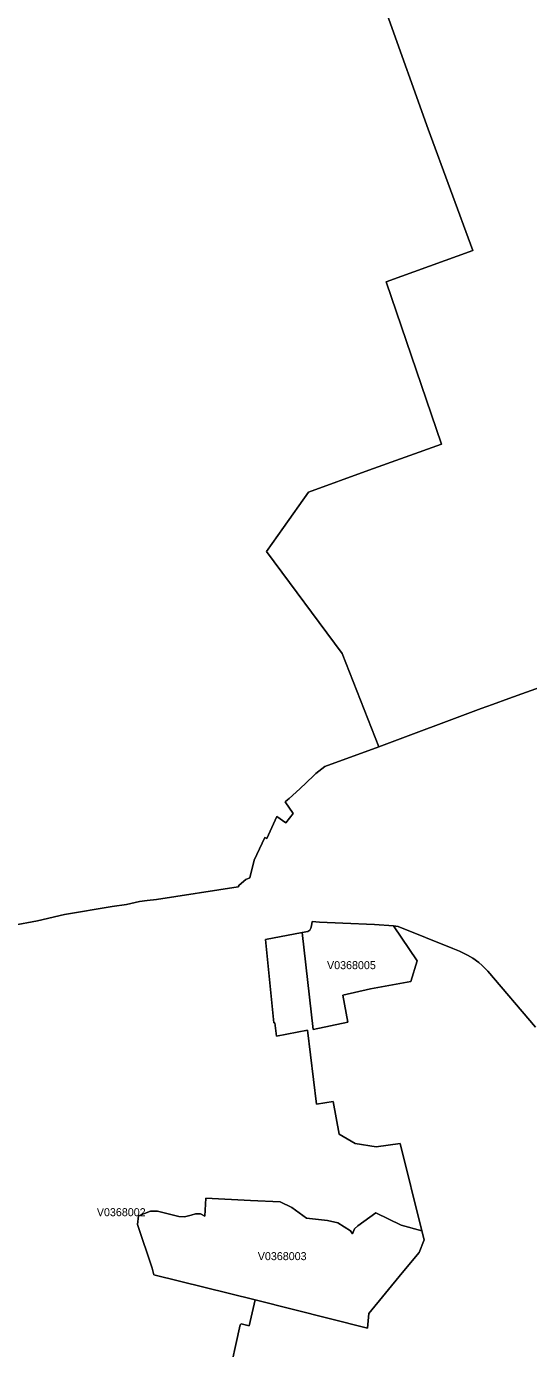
# Model space of a CAD drawing. Extents: x 369010 to 735936, y 6377141 to 6616555.
# Drawn here: x 420580 to 426855, y 6521309 to 6537827 of the extents above; entities that cross this region are included whole.
import ezdxf
from ezdxf.enums import TextEntityAlignment as Align

# ---------------------------------------------------------------- set-up
doc = ezdxf.new("R2010")
doc.units = 0
doc.header["$LTSCALE"] = 40
doc.layers.add('3', color=7, linetype='Continuous', lineweight=13)
doc.layers.add('4', color=7, linetype='Continuous')

msp = doc.modelspace()

# ---------------------------------------------------------------- linework, layer by layer
at = {"layer": '3'}
for points in [[(424415.81, 6546307.59), (424374.6, 6546292.36), (424272.82, 6546261.91), (423933.2, 6546139.93), (422029.25, 6545457.73), (423467.15, 6541434.49), (423806.93, 6541545.87), (424061.64, 6540845.46), (425600.49, 6536542.36), (426160.06, 6535027.83), (425074.19, 6534636.25), (425765.33, 6532609.98), (424859.86, 6532281.79), (424104.67, 6532007.05), (423793.52, 6531567.14), (423578.53, 6531267.41), (424524.72, 6529994.03), (424983.49, 6528828.21), (426261.85, 6529304.37), (426404.84, 6529356.34), (426607.91, 6529430.15), (427110.22, 6529610.72)], [(423226.67, 6527076.19), (423237.92, 6527099.36), (423323.16, 6527167.55), (423370.99, 6527189.39), (423426.43, 6527412.82), (423492.3, 6527553.83), (423558.34, 6527694.84), (423582.83, 6527682.76), (423711.43, 6527957.5), (423821.49, 6527876.07), (423915.33, 6527993.08), (423815.03, 6528138.56), (423843.34, 6528163.39), (423863.69, 6528180.43), (423998.58, 6528303.9), (424168.88, 6528465.1), (424195.69, 6528491.91), (424307.91, 6528582.61), (424983.49, 6528828.21), (424524.72, 6529994.03), (423578.53, 6531267.41), (423793.52, 6531567.14), (424104.67, 6532007.05), (424859.86, 6532281.79), (425765.33, 6532609.98), (425074.19, 6534636.25), (426160.06, 6535027.83), (425600.49, 6536542.36), (424061.64, 6540845.46)], [(427110.22, 6529610.72), (426607.91, 6529430.15), (426404.84, 6529356.34), (426261.85, 6529304.37), (424983.49, 6528828.21)], [(424983.49, 6528828.21), (424307.91, 6528582.61), (424195.69, 6528491.91), (424168.88, 6528465.1), (423998.58, 6528303.9), (423863.69, 6528180.43), (423843.34, 6528163.39), (423815.03, 6528138.56), (423915.33, 6527993.08), (423821.49, 6527876.07), (423711.43, 6527957.5), (423582.83, 6527682.76), (423558.34, 6527694.84), (423492.3, 6527553.83), (423426.43, 6527412.82), (423370.99, 6527189.39), (423323.16, 6527167.55), (423237.92, 6527099.36), (423226.67, 6527076.19), (422206, 6526921.61), (422089.66, 6526908.53), (421991.02, 6526894.3), (421830.81, 6526856.9), (421650.57, 6526833.23), (421056.08, 6526732.27), (420717.3, 6526654.49), (420407.64, 6526594.74)], [(420407.64, 6526594.74), (420717.3, 6526654.49), (421056.08, 6526732.27), (421650.57, 6526833.23), (421830.81, 6526856.9), (421991.02, 6526894.3), (422089.66, 6526908.53), (422206, 6526921.61), (423226.67, 6527076.19)], [(426940.08, 6525323.67), (426344.76, 6526022.43), (426276.91, 6526095.74), (426234.87, 6526134.31), (426157.74, 6526186.94), (426093.03, 6526223.68), (425991.41, 6526272.67), (425909.16, 6526309.41), (425226.78, 6526580.84), (425169.35, 6526590.1), (425461.3, 6526153.5), (425386, 6525894.33), (424878.89, 6525805.28), (424535.64, 6525724.68), (424598.7, 6525388.55), (424161.77, 6525297.52), (424026.88, 6526505.7), (423567.77, 6526421.12), (423672.7, 6525377.29), (423683.29, 6525378.28), (423704.31, 6525211.79), (424091.26, 6525288.91), (424203.14, 6524361.59), (424413.33, 6524394.86), (424488.64, 6523986.89), (424690.05, 6523871.2), (424949.23, 6523830.99), (425250.29, 6523871.2), (425522.21, 6522781.86), (425550.84, 6522667.33), (425486.13, 6522509.77), (425275.94, 6522255.89), (424861.19, 6521747.95), (424843.97, 6521564.58), (423440.5, 6521918.42), (423363.71, 6521593.54), (423265.56, 6521616.87), (423249.51, 6521604.3), (423095.92, 6520904.55)], [(424690.05, 6523871.2), (424488.64, 6523986.89), (424413.33, 6524394.86), (424203.14, 6524361.59), (424091.26, 6525288.91), (423704.31, 6525211.79), (423683.29, 6525378.28), (423672.7, 6525377.29), (423567.77, 6526421.12), (424026.88, 6526505.7), (424096.89, 6526520.59), (424121.38, 6526534.66), (424135.45, 6526559.98), (424143.39, 6526592.42), (424151.17, 6526645.05), (424241.37, 6526637.94), (424534.65, 6526623.04), (424928.88, 6526608.31), (425169.35, 6526590.1), (425226.78, 6526580.84), (425909.16, 6526309.41), (425991.41, 6526272.67), (426093.03, 6526223.68), (426157.74, 6526186.94), (426234.87, 6526134.31), (426276.91, 6526095.74), (426344.76, 6526022.43), (426940.08, 6525323.67)], [(423095.92, 6520904.55), (423249.51, 6521604.3), (423265.56, 6521616.87), (423363.71, 6521593.54), (423440.5, 6521918.42), (422173.4, 6522232.22), (422152.22, 6522312.65), (421968.34, 6522859.15), (421982.24, 6522966.06), (422129.38, 6523023.82), (422216.93, 6523025.48), (422285.28, 6523009.76), (422483.06, 6522957.29), (422556.71, 6522955.47), (422640.62, 6522976.49), (422693.25, 6522994.03), (422754.49, 6522990.56), (422808.77, 6522964.24), (422821.02, 6523188.34), (423379.59, 6523160.37), (423749.99, 6523144.48), (423895.3, 6523072.65), (424079.18, 6522939.58), (424343.49, 6522908.14), (424470.43, 6522880.33), (424629.81, 6522778.71), (424654.31, 6522741.97), (424678.8, 6522803.21), (424720.84, 6522841.77), (424946.75, 6523004.63), (425263.03, 6522850.21), (425522.21, 6522781.86), (425250.29, 6523871.2), (424949.23, 6523830.99), (424690.05, 6523871.2)]]:
    msp.add_lwpolyline(points, dxfattribs=at)
for points in [[(424026.88, 6526505.7), (424161.77, 6525297.52), (424598.7, 6525388.55), (424535.64, 6525724.68), (424878.89, 6525805.28), (425386, 6525894.33), (425461.3, 6526153.5), (425169.35, 6526590.1), (424928.88, 6526608.31), (424534.65, 6526623.04), (424241.37, 6526637.94), (424151.17, 6526645.05), (424143.39, 6526592.42), (424135.45, 6526559.98), (424121.38, 6526534.66), (424096.89, 6526520.59)], [(423440.5, 6521918.42), (424843.97, 6521564.58), (424861.19, 6521747.95), (425275.94, 6522255.89), (425486.13, 6522509.77), (425550.84, 6522667.33), (425522.21, 6522781.86), (425263.03, 6522850.21), (424946.75, 6523004.63), (424720.84, 6522841.77), (424678.8, 6522803.21), (424654.31, 6522741.97), (424629.81, 6522778.71), (424470.43, 6522880.33), (424343.49, 6522908.14), (424079.18, 6522939.58), (423895.3, 6523072.65), (423749.99, 6523144.48), (423379.59, 6523160.37), (422821.02, 6523188.34), (422808.77, 6522964.24), (422754.49, 6522990.56), (422693.25, 6522994.03), (422640.62, 6522976.49), (422556.71, 6522955.47), (422483.06, 6522957.29), (422285.28, 6523009.76), (422216.93, 6523025.48), (422129.38, 6523023.82), (421982.24, 6522966.06), (421968.34, 6522859.15), (422152.22, 6522312.65), (422173.4, 6522232.22)]]:
    msp.add_lwpolyline(points, close=True, dxfattribs=at)

# ---------------------------------------------------------------- texts
at = {"layer": '4'}
for s, p in [('V0368005', (424641.42, 6526049.31)), ('V0368002', (421764.86, 6522963.11)), ('V0368003', (423776.28, 6522413.97))]:
    msp.add_text(s, height=100, dxfattribs=at).set_placement(p, align=Align.CENTER)

doc.saveas('drawing.dxf')
